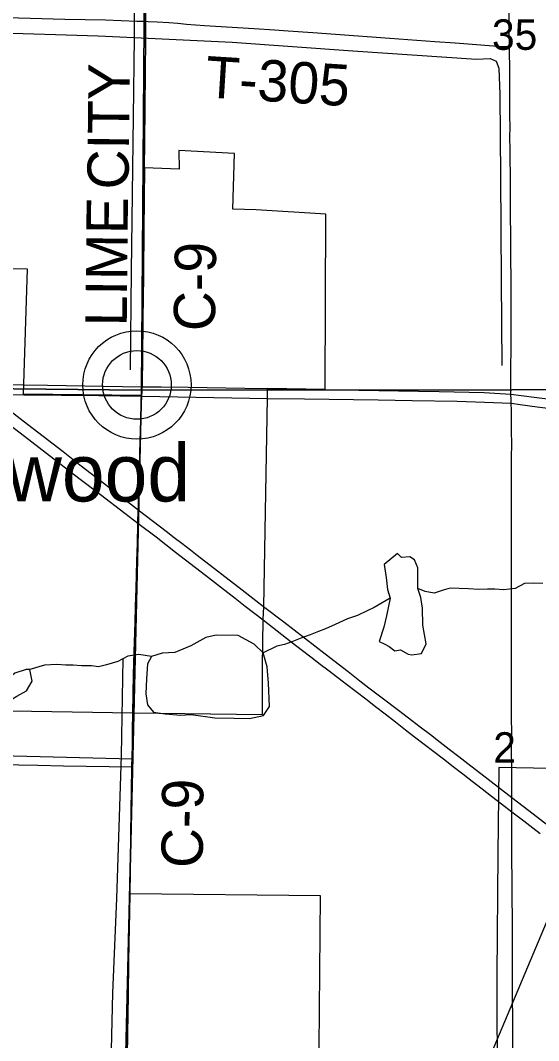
# Model space of a CAD drawing. Extents: x 0 to 34, y 0 to 22.
# Drawn here: x 6.331 to 7.043, y 16.982 to 18.383 of the extents above; entities that cross this region are included whole.
import ezdxf

# ---------------------------------------------------------------- set-up
doc = ezdxf.new("R2010")
doc.units = 0
for name, color, linetype in [('GM_X_City_Street', 7, 'Continuous'), ('GM_X_Corporation', 7, 'Continuous'), ('GM_X_County_Road', 7, 'Continuous'), ('GM_X_County_Road_Text', 7, 'Continuous'), ('GM_X_Interstate_Route', 7, 'Continuous'), ('GM_X_Minor_Lake', 7, 'Continuous'), ('GM_X_Minor_River', 7, 'Continuous'), ('GM_X_Rail_Line', 7, 'Continuous'), ('GM_X_Section_Text', 7, 'Continuous'), ('GM_X_State_Route', 7, 'Continuous'), ('GM_X_Township_Road', 7, 'Continuous'), ('GM_X_Township_Road_Text', 7, 'Continuous'), ('GM_X_Unincorporated', 7, 'Continuous'), ('GM_X_Unincorporated_Location', 7, 'Continuous'), ('GM_X_Unincorporated_Text', 7, 'Continuous')]:
    doc.layers.add(name, color=color, linetype=linetype)

msp = doc.modelspace()

# ---------------------------------------------------------------- linework, layer by layer
at = {"layer": 'GM_X_City_Street'}
msp.add_lwpolyline([(5.8712, 17.4463), (5.882, 17.4431), (5.8854, 17.442), (5.9101, 17.4346), (5.9523, 17.4234), (5.9916, 17.4133), (6.0278, 17.4038), (6.0821, 17.3898), (6.1334, 17.3764), (6.1546, 17.371), (6.1667, 17.3682), (6.1748, 17.3665), (6.1833, 17.3652), (6.1911, 17.3643), (6.1992, 17.3636), (6.2141, 17.363), (6.2478, 17.3624), (6.2787, 17.3618), (6.3287, 17.3611), (6.3546, 17.3607), (6.3897, 17.3599), (6.4838, 17.3584)], dxfattribs=at)
at = {"layer": 'GM_X_Corporation'}
for points in [[(5.7555, 18.8946), (5.9964, 18.8894), (6.5045, 18.8781), (6.497, 17.8754), (5.4886, 17.8861), (5.4973, 18.4037), (5.5066, 18.8978)], [(6.5045, 18.8781), (7.0065, 18.8908), (7.5285, 18.8343), (7.515, 17.8763), (6.497, 17.8754)], [(5.4886, 17.8861), (6.497, 17.8754), (6.4745, 16.9262), (5.4784, 16.9512)], [(6.497, 17.8754), (7.515, 17.8763), (7.4991, 16.9078), (6.4745, 16.9262)]]:
    msp.add_lwpolyline(points, close=True, dxfattribs=at)
for points in [[(6.2899, 17.4358), (6.4851, 17.4326), (6.6633, 17.43), (6.6633, 17.4961), (6.6642, 17.5606), (6.6654, 17.5782), (6.6704, 17.8648), (6.6702, 17.8783), (6.7493, 17.8767), (6.7503, 18.117), (6.6547, 18.1229), (6.6224, 18.1241), (6.625, 18.2006), (6.5485, 18.2048), (6.5486, 18.1791), (6.5011, 18.1806), (6.4978, 17.8809), (6.4966, 17.868), (6.3349, 17.8699), (6.3405, 18.0415), (6.2862, 18.0425)], [(6.7407, 16.9204), (6.7429, 17.181), (6.4815, 17.1838), (6.4842, 17.369), (6.249, 17.3747)]]:
    msp.add_lwpolyline(points, dxfattribs=at)
at = {"layer": 'GM_X_County_Road'}
for p, q in [((6.4976, 17.8674), (6.4979, 17.8741)), ((6.4979, 17.8741), (6.498, 17.8803))]:
    msp.add_line(p, q, dxfattribs=at)
for points in [[(6.5013, 18.1797), (6.5013, 18.1801), (6.5016, 18.216), (6.5029, 18.3589), (6.503, 18.382), (6.5032, 18.4397), (6.5035, 18.4925), (6.5038, 18.5639), (6.5038, 18.6327)], [(6.498, 17.8803), (6.4981, 17.9064), (6.4991, 17.9595), (6.5001, 18.0282), (6.5013, 18.1797)], [(6.4929, 17.7202), (6.4935, 17.7402), (6.4945, 17.7713), (6.4953, 17.8056), (6.496, 17.8344), (6.4966, 17.8463), (6.4976, 17.8674)], [(6.4853, 17.4311), (6.4853, 17.4321), (6.4862, 17.485), (6.4869, 17.5161), (6.4884, 17.5566), (6.489, 17.5784), (6.4897, 17.6033), (6.4906, 17.6406), (6.4914, 17.6655), (6.492, 17.6904), (6.4921, 17.693), (6.4926, 17.711), (6.4928, 17.7153), (6.4929, 17.7202)], [(6.4838, 17.3584), (6.4846, 17.3875), (6.4847, 17.4096), (6.4853, 17.4311)], [(6.4814, 17.1837), (6.4819, 17.2197), (6.4823, 17.2631), (6.4829, 17.3006), (6.4832, 17.3251), (6.4838, 17.3584)], [(6.4774, 16.9235), (6.4774, 16.9274), (6.4782, 16.9927), (6.4787, 17.0176), (6.4793, 17.0455), (6.4797, 17.089), (6.4803, 17.117), (6.4807, 17.1356), (6.4814, 17.1837)]]:
    msp.add_lwpolyline(points, dxfattribs=at)
at = {"layer": 'GM_X_Interstate_Route'}
for points in [[(6.2545, 17.8744), (6.2601, 17.8702), (6.2744, 17.8591), (6.2982, 17.8411), (6.3365, 17.8123), (6.3665, 17.7892), (6.4108, 17.7549), (6.4405, 17.7323), (6.4742, 17.7067), (6.4921, 17.693), (6.5171, 17.6739), (6.5436, 17.6532), (6.585, 17.6213), (6.6056, 17.6053), (6.6258, 17.5897), (6.6395, 17.579), (6.6644, 17.56)], [(6.2988, 17.861), (6.3343, 17.8336), (6.3895, 17.7911), (6.4125, 17.7731), (6.4434, 17.749), (6.4901, 17.7129), (6.4926, 17.711), (6.5326, 17.6805), (6.54, 17.6748), (6.542, 17.6733), (6.5524, 17.6654), (6.5642, 17.6562), (6.5735, 17.649), (6.6353, 17.6012), (6.6647, 17.5783), (6.6925, 17.5574), (6.7496, 17.5133), (6.7811, 17.489), (6.7973, 17.4764), (6.8096, 17.4669), (6.8278, 17.4529), (6.8501, 17.4359), (6.8798, 17.4134), (6.8942, 17.4025), (6.9075, 17.3923), (6.9198, 17.3828), (6.933, 17.3725), (6.9453, 17.3629), (6.9734, 17.3413), (7.0059, 17.3164), (7.0291, 17.2985), (7.0616, 17.2735)], [(6.6644, 17.56), (6.7027, 17.5301), (6.7184, 17.518), (6.7298, 17.5093), (6.7427, 17.4995), (6.753, 17.4916), (6.7668, 17.481), (6.7787, 17.4719), (6.792, 17.4617), (6.8053, 17.4515), (6.8186, 17.4412), (6.8319, 17.431), (6.8461, 17.4199), (6.8599, 17.4093), (6.8722, 17.3997), (6.8855, 17.3895), (6.8987, 17.3792), (6.9121, 17.3691), (6.9254, 17.3588), (6.9387, 17.3486), (6.9514, 17.3387), (6.9653, 17.3281), (6.978, 17.3182), (6.9919, 17.3076), (7.0059, 17.2967), (7.0224, 17.2841), (7.0347, 17.2746), (7.045, 17.2666)]]:
    msp.add_lwpolyline(points, dxfattribs=at)
at = {"layer": 'GM_X_Minor_Lake'}
for p, q in [((6.8769, 17.6151), (6.8767, 17.6315)), ((6.5651, 17.4304), (6.5979, 17.4258))]:
    msp.add_line(p, q, dxfattribs=at)
for points in [[(6.8767, 17.6315), (6.8723, 17.6425), (6.8656, 17.6468), (6.8542, 17.6458), (6.849, 17.6512), (6.8303, 17.6362), (6.8331, 17.6184), (6.8351, 17.602), (6.8388, 17.5898), (6.8339, 17.5656), (6.8299, 17.5501), (6.8236, 17.5304), (6.8315, 17.5269), (6.8375, 17.5234), (6.8454, 17.5176), (6.853, 17.519), (6.8635, 17.5128), (6.8687, 17.512), (6.882, 17.5141), (6.8882, 17.5273), (6.8836, 17.5528), (6.8832, 17.576), (6.8811, 17.5908), (6.8767, 17.6034), (6.8769, 17.6151)], [(6.5979, 17.4258), (6.6243, 17.4251), (6.6455, 17.4245), (6.6648, 17.4288), (6.6729, 17.4412), (6.6718, 17.4731), (6.6698, 17.4955), (6.6644, 17.5149), (6.6517, 17.5269), (6.6299, 17.5385), (6.5997, 17.5389), (6.5853, 17.5361), (6.5648, 17.5245), (6.5431, 17.5153), (6.5254, 17.5144), (6.5106, 17.5097), (6.5055, 17.4999), (6.5038, 17.479), (6.5031, 17.4585), (6.5052, 17.4433), (6.5137, 17.4333), (6.5296, 17.4312), (6.5511, 17.4291), (6.5651, 17.4304)], [(6.2927, 17.4327), (6.3137, 17.448), (6.3259, 17.4554), (6.3392, 17.4625), (6.3466, 17.476), (6.3438, 17.492), (6.3385, 17.4921), (6.3229, 17.487), (6.3095, 17.4754), (6.2912, 17.4585), (6.2785, 17.4443), (6.2671, 17.4338), (6.2443, 17.4268), (6.2302, 17.4198), (6.215, 17.4075), (6.2035, 17.3947), (6.206, 17.3818), (6.2184, 17.3809), (6.229, 17.3849), (6.2401, 17.3946), (6.252, 17.4051), (6.2657, 17.414)]]:
    msp.add_lwpolyline(points, dxfattribs=at)
at = {"layer": 'GM_X_Minor_River'}
for points in [[(6.4979, 19.7966), (6.4943, 19.6031), (6.4917, 19.4669), (6.4921, 19.2904), (6.4898, 19.0605), (6.4887, 18.7982), (6.487, 18.555), (6.4868, 18.3599), (6.4854, 18.2509), (6.483, 18.0388), (6.4816, 17.9033)], [(6.1088, 18.3726), (6.2901, 18.3665), (6.4373, 18.362), (6.4868, 18.3599), (6.6216, 18.3532), (6.7876, 18.3413), (6.9575, 18.33), (6.976, 18.331), (6.9843, 18.3271), (6.9879, 18.3175), (6.9893, 18.2814), (6.9905, 18.1683), (6.9913, 18.0263), (6.9921, 17.9094)], [(7.0487, 17.61), (7.0362, 17.6105), (7.0234, 17.6099), (7.0104, 17.6032), (6.9949, 17.6015), (6.9828, 17.6021), (6.9726, 17.6022), (6.9606, 17.602), (6.9466, 17.6025), (6.9338, 17.6034), (6.9213, 17.6036), (6.9118, 17.601), (6.8993, 17.597), (6.8869, 17.5991), (6.8767, 17.6034)], [(7.094, 17.6126), (7.1052, 17.5724), (7.1111, 17.5594), (7.114, 17.5469), (7.1138, 17.5306), (7.1129, 17.4953), (7.1066, 17.3549), (6.988, 17.3575), (6.9865, 17.2387), (6.9855, 17.0721), (6.986, 16.9066), (6.981, 16.729), (6.9765, 16.5845), (6.9664, 16.3614)], [(6.8388, 17.5898), (6.8167, 17.5772), (6.8072, 17.5724), (6.7939, 17.5661), (6.7802, 17.5617), (6.7631, 17.5539), (6.7498, 17.548), (6.7403, 17.544), (6.7289, 17.5396), (6.7175, 17.5355), (6.7035, 17.53), (6.6936, 17.5263), (6.683, 17.5238), (6.6644, 17.5149)], [(6.5106, 17.5097), (6.4932, 17.5127), (6.4785, 17.5101), (6.4644, 17.503), (6.4492, 17.4983), (6.4382, 17.4954), (6.4284, 17.497), (6.4145, 17.4972), (6.4031, 17.4977), (6.3933, 17.4979), (6.3805, 17.4988), (6.3637, 17.498), (6.3438, 17.492)], [(6.4716, 17.5067), (6.4692, 17.3739), (6.4629, 17.1777), (6.4574, 17.048), (6.4541, 16.911), (6.4528, 16.8389)]]:
    msp.add_lwpolyline(points, dxfattribs=at)
at = {"layer": 'GM_X_Rail_Line'}
msp.add_lwpolyline([(5.7724, 14.1), (5.9023, 14.4065), (6.108, 14.9012), (7.0925, 17.2371), (7.3462, 17.8422), (7.5826, 18.397), (7.8741, 19.1084), (7.9022, 19.1708), (7.9338, 19.2375), (7.9584, 19.2815), (7.9927, 19.3184), (8.0524, 19.3602), (8.3458, 19.5368)], dxfattribs=at)
at = {"layer": 'GM_X_State_Route'}
for p, q in [((6.6714, 17.8778), (6.7496, 17.8762)), ((6.4976, 17.8674), (6.6707, 17.8642))]:
    msp.add_line(p, q, dxfattribs=at)
for points in [[(5.6374, 17.8921), (5.6437, 17.8921), (5.6605, 17.8918), (5.7436, 17.8909), (5.7716, 17.8905), (5.8183, 17.8896), (5.8525, 17.8891), (5.896, 17.8883), (5.9021, 17.8881), (5.908, 17.8879), (5.9383, 17.8871), (6.0018, 17.8861), (6.0391, 17.8858), (6.0826, 17.8851), (6.1169, 17.885), (6.1822, 17.8842), (6.2195, 17.8838), (6.2427, 17.8836), (6.2506, 17.8835), (6.2698, 17.8833), (6.3357, 17.8827)], [(6.3357, 17.8827), (6.3677, 17.8823), (6.4194, 17.8814), (6.4964, 17.8803), (6.498, 17.8803)], [(6.498, 17.8803), (6.5241, 17.8801), (6.5614, 17.8797), (6.6392, 17.8783), (6.6704, 17.8778), (6.6714, 17.8778)], [(6.7496, 17.8762), (6.7683, 17.8759), (6.8779, 17.8743), (6.9059, 17.8739), (6.9678, 17.8722), (6.9897, 17.871), (7.0048, 17.8698), (7.0188, 17.8681), (7.0404, 17.8655), (7.0663, 17.8622)], [(6.2295, 17.8705), (6.2468, 17.8703), (6.2601, 17.8702), (6.281, 17.8699), (6.2874, 17.8698), (6.3352, 17.8693)], [(6.3352, 17.8693), (6.4385, 17.8683), (6.4969, 17.8674), (6.4976, 17.8674)], [(6.6707, 17.8642), (6.721, 17.8637), (6.8222, 17.8621), (6.8688, 17.8613), (6.931, 17.8603), (6.9683, 17.8592), (7.0051, 17.8575), (7.0176, 17.8559), (7.041, 17.8528), (7.07, 17.8488)]]:
    msp.add_lwpolyline(points, dxfattribs=at)
at = {"layer": 'GM_X_Township_Road'}
for points in [[(7.0027, 18.3472), (7.0026, 18.3511), (7.0025, 18.3629), (7.0021, 18.3978), (7.0023, 18.4152), (7.0024, 18.4425), (7.0024, 18.4544), (7.0025, 18.4643), (7.0023, 18.4836), (7.0026, 18.5047), (7.0026, 18.5172), (7.0029, 18.5314), (7.0027, 18.5439), (7.0027, 18.5588), (7.0026, 18.5799), (7.0026, 18.6054), (7.0025, 18.6198)], [(6.0725, 18.3922), (6.0744, 18.3924), (6.0774, 18.3927), (6.09, 18.3926), (6.1395, 18.3914), (6.1452, 18.3913), (6.18, 18.3905), (6.2204, 18.3894), (6.2581, 18.3887), (6.2959, 18.3877), (6.3915, 18.3851), (6.4475, 18.3838), (6.4906, 18.3823), (6.503, 18.382)], [(6.503, 18.382), (6.5062, 18.3819), (6.5186, 18.3811), (6.5344, 18.3804), (6.5472, 18.3792), (6.5589, 18.3782), (6.5837, 18.3763), (6.6518, 18.3719), (6.6798, 18.3701), (6.6984, 18.3688), (6.7325, 18.3664), (6.7635, 18.3641), (6.8385, 18.3588), (6.9, 18.3544), (6.9279, 18.3522), (6.9807, 18.3485), (6.9965, 18.3475), (7.0027, 18.3472)], [(7.0051, 17.8575), (7.005, 17.8623), (7.0048, 17.8698), (7.0047, 17.8787), (7.0047, 17.8878), (7.0047, 17.9121), (7.0049, 17.9273), (7.0052, 17.9481), (7.0052, 17.9792), (7.005, 17.9904), (7.005, 18.0022), (7.0049, 18.0171), (7.0049, 18.0352), (7.0048, 18.0495), (7.0045, 18.0868), (7.0043, 18.1166), (7.0043, 18.1306), (7.0042, 18.1443), (7.0042, 18.1572), (7.0039, 18.1771), (7.0038, 18.187), (7.0036, 18.2048), (7.0034, 18.2237), (7.0035, 18.2355), (7.0032, 18.2529), (7.0031, 18.2766), (7.0031, 18.3101), (7.0027, 18.3472)], [(7.0073, 16.9523), (7.0073, 17.0077), (7.0073, 17.0201), (7.007, 17.0332), (7.0068, 17.0474), (7.0068, 17.0561), (7.0068, 17.1475), (7.0065, 17.1817), (7.0065, 17.1985), (7.0061, 17.2364), (7.0061, 17.2513), (7.0061, 17.2616), (7.006, 17.2695), (7.006, 17.2767), (7.0059, 17.2967), (7.0059, 17.3164), (7.0058, 17.3415), (7.0059, 17.3577), (7.0056, 17.3813), (7.0058, 17.4068), (7.0055, 17.4242), (7.0053, 17.4428), (7.0055, 17.4786), (7.0056, 17.4926), (7.0057, 17.5114), (7.0057, 17.5211), (7.0057, 17.5522), (7.0057, 17.5689), (7.0057, 17.592), (7.0057, 17.6083), (7.0057, 17.6235), (7.0057, 17.6293), (7.0056, 17.6516), (7.0055, 17.6728), (7.0055, 17.6963), (7.0055, 17.7162), (7.0056, 17.7356), (7.0056, 17.7654), (7.0056, 17.7834), (7.0058, 17.8008), (7.0057, 17.8201), (7.0056, 17.8388), (7.0054, 17.8476), (7.0051, 17.8575)]]:
    msp.add_lwpolyline(points, dxfattribs=at)
at = {"layer": 'GM_X_Unincorporated'}
for radius in [0.0744, 0.0472]:
    msp.add_circle((6.4908, 17.8827), radius, dxfattribs=at)
at = {"layer": 'GM_X_Unincorporated_Location'}
msp.add_line((6.4908, 17.8827), (6.4908, 17.8827), dxfattribs=at)

# ---------------------------------------------------------------- texts
at = {"layer": 'GM_X_County_Road_Text'}
for s, rotation, p in [('CITY', 89.4109, (6.4793, 18.1509)), ('LIME', 89.4386, (6.4768, 17.963)), ('C-9', 89.0838, (6.5979, 17.9562)), ('C-9', 89.5421, (6.5812, 17.2193))]:
    msp.add_text(s, height=0.05682, rotation=rotation, dxfattribs=at).set_placement(p)
at = {"layer": 'GM_X_Section_Text'}
for s, height, p in [('35', 0.04186, (6.9787, 18.3428)), ('2', 0.0419, (6.9804, 17.3639))]:
    msp.add_text(s, height=height, rotation=0, dxfattribs=at).set_placement(p)
at = {"layer": 'GM_X_Township_Road_Text'}
msp.add_text('T-305', height=0.05682, rotation=356.3888, dxfattribs=at).set_placement((6.5836, 18.2777))
at = {"layer": 'GM_X_Unincorporated_Text'}
msp.add_text('Glenwood', height=0.07898, rotation=0, dxfattribs=at).set_placement((6.0883, 17.7227))

doc.saveas('drawing.dxf')
